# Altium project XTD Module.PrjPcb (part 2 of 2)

## Sheet IDL_17_004_A8.SchDoc: Power
size 401 x 291 mm
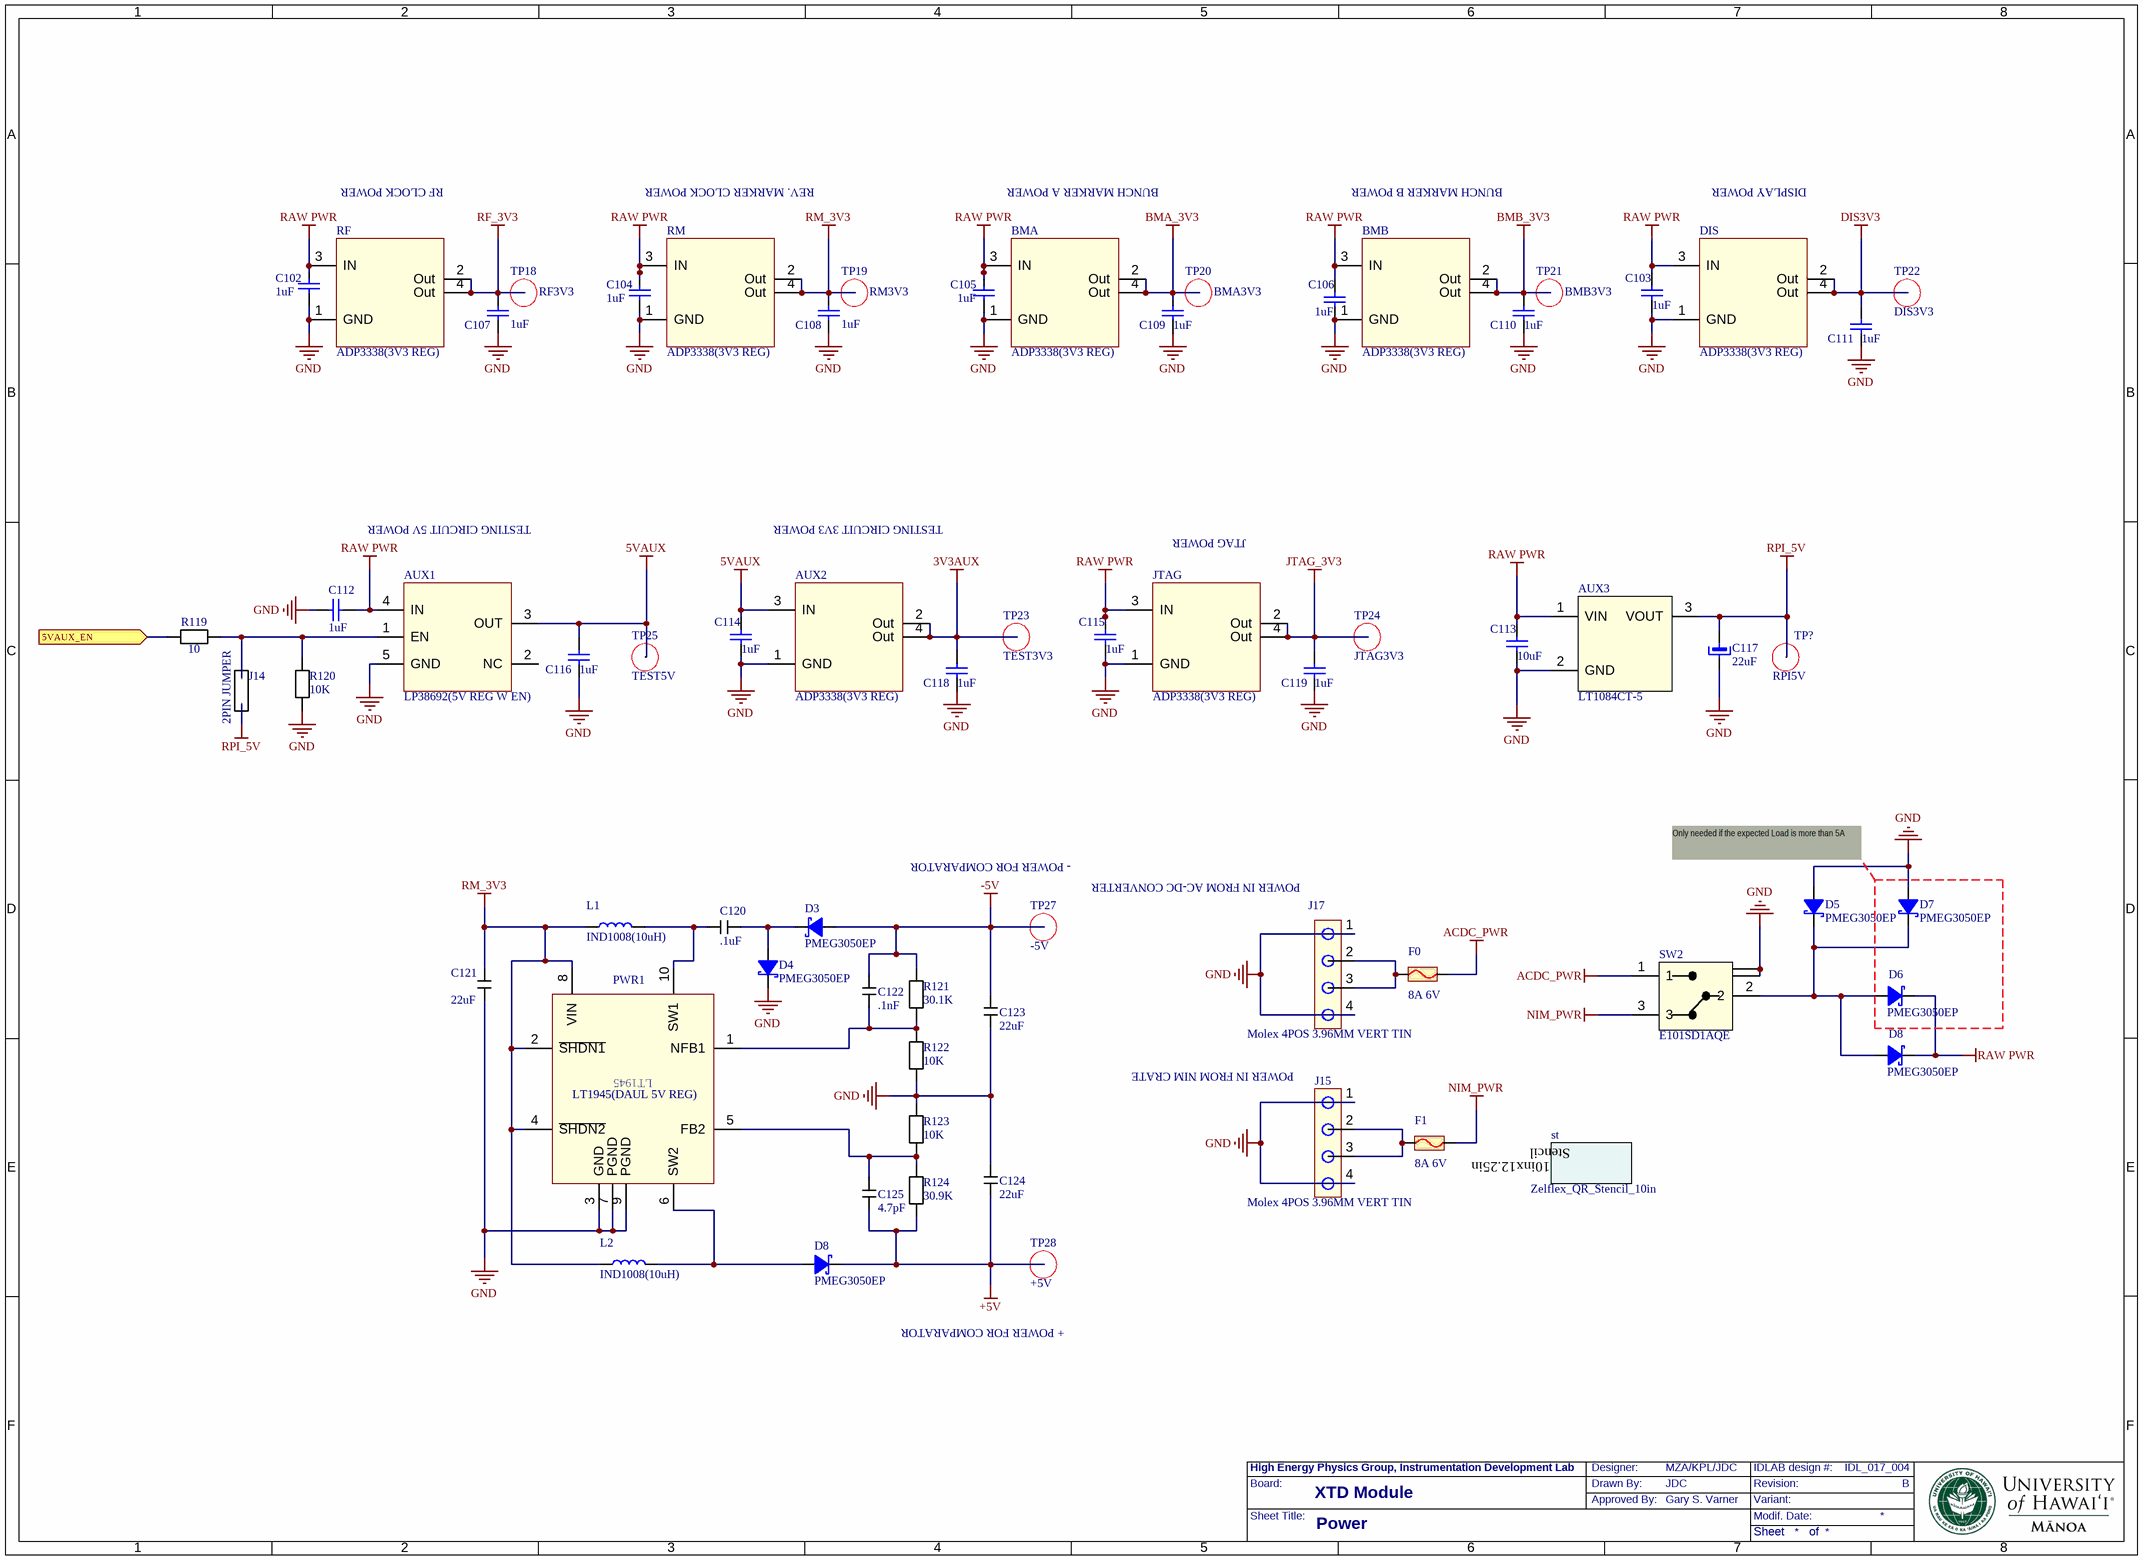
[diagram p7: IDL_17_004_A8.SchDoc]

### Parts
(Parts that share a designator on the sheet are numbered #1, #2 ... from top to bottom, then left to right.)
AUX1  LP38692(5V REG W EN)  [SOT223_5pin]
AUX2  ADP3338(3V3 REG)  [ADP3338]
AUX3  LT1084CT-5  [TO220H]
BMA  ADP3338(3V3 REG)  [ADP3338]
BMB  ADP3338(3V3 REG)  [ADP3338]
C102  1uF  [0603]
C103  1uF  [0603]
C104  1uF  [0603]
C105  1uF  [0603]
C106  1uF  [0603]
C107  1uF  [0603]
C108  1uF  [0603]
C109  1uF  [0603]
C110  1uF  [0603]
C111  1uF  [0603]
C112  1uF  [0603]
C113  10uF  [0603]
C114  1uF  [0603]
C115  1uF  [0603]
C116  1uF  [0603]
C117  22uF  [CTC-D7343-31]
C118  1uF  [0603]
C119  1uF  [0603]
C120  .1uF  [0603]
C121  22uF  [0603]
C122  .1nF  [0603]
C123  22uF  [0603]
C124  22uF  [0603]
C125  4.7pF  [0603]
D3  PMEG3050EP  [SOD128]
D4  PMEG3050EP  [SOD128]
D5  PMEG3050EP  [SOD128]
D6  PMEG3050EP  [SOD128]
D7  PMEG3050EP  [SOD128]
D8#1  PMEG3050EP  [SOD128]
D8#2  PMEG3050EP  [SOD128]
DIS  ADP3338(3V3 REG)  [ADP3338]
F0  8A 6V  [FUSE1206-1]
F1  8A 6V  [FUSE1206-1]
J14  2PIN JUMPER  [2 PIN HEADER]
J15  Molex 4POS 3.96MM VERT TIN  [Molex 4POS]
J17  Molex 4POS 3.96MM VERT TIN  [Molex 4POS]
JTAG  ADP3338(3V3 REG)  [ADP3338]
L1  IND1008(10uH)  [1008]
L2  IND1008(10uH)  [1008]
PWR1  LT1945(DAUL 5V REG)  [TFSOP_10pin]
R119  10  [0402]
R120  10K  [0402]
R121  30.1K  [0402]
R122  10K  [0402]
R123  10K  [0402]
R124  30.9K  [0402]
RF  ADP3338(3V3 REG)  [ADP3338]
RM  ADP3338(3V3 REG)  [ADP3338]
st  Zelflex_QR_Stencil_10in  [Zelflex_QR_Stencil_10in]
SW2  E101SD1AQE  [E101SD1AQE]
TP18  RF3V3  [Test Point]
TP19  RM3V3  [Test Point]
TP20  BMA3V3  [Test Point]
TP21  BMB3V3  [Test Point]
TP22  DIS3V3  [Test Point]
TP23  TEST3V3  [Test Point]
TP24  JTAG3V3  [Test Point]
TP25  TEST5V  [Test Point]
TP27  -5V  [Test Point]
TP28  +5V  [Test Point]
TP?  RPI5V  [Test Point]

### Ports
5VAUX_EN (in)

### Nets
3V3AUX: AUX2.2(Out) AUX2.4(Out) C118.2 TP23.1(TP)
5VAUX: AUX1.3(OUT) AUX2.3(IN) C114.2 C116.2 TP25.1(TP)
+5V: C124.1 C125.2 D8#2.1(C) R124.1 TP28.1(TP)
-5V: C122.2 C123.2 D3.2(A) R121.2 TP27.1(TP)
ACDC_PWR: F0.2 SW2.1
BMA_3V3: BMA.2(Out) BMA.4(Out) C109.2 TP20.1(TP)
BMB_3V3: BMB.2(Out) BMB.4(Out) C110.2 TP21.1(TP)
DIS3V3: C111.2 DIS.2(Out) DIS.4(Out) TP22.1(TP)
GND: AUX1.5(GND) AUX2.1(GND) AUX3.2(GND) BMA.1(GND) BMB.1(GND) C102.1 C103.1 C104.1 C105.1 C106.1 C107.1 C108.1 C109.1 C110.1 C111.1 C112.2 C113.1 C114.1 C115.1 C116.1 C117.2 C118.1 C119.1 C121.1 C123.1 C124.2 D4.1(C) D5.2(A) D7.2(A) DIS.1(GND) J15.1 J15.4 J17.1 J17.4 JTAG.1(GND) PWR1.3(GND) PWR1.7(PGND) PWR1.9(PGND) R120.1 R122.2 R123.1 RF.1(GND) RM.1(GND) SW2.4 SW2.5
JTAG_3V3: C119.2 JTAG.2(Out) JTAG.4(Out) TP24.1(TP)
NIM_PWR: F1.2 SW2.3
RAW PWR: AUX1.4(IN) AUX3.1(VIN) BMA.3(IN) BMB.3(IN) C102.2 C103.2 C104.2 C105.2 C106.2 C112.1 C113.2 C115.2 D6.1(C) D8#1.1(C) DIS.3(IN) JTAG.3(IN) RF.3(IN) RM.3(IN)
RF_3V3: C107.2 RF.2(Out) RF.4(Out) TP18.1(TP)
RM_3V3: C108.2 C121.2 L1.1 L2.1 PWR1.2(~{SHDN1}) PWR1.4(~{SHDN2}) PWR1.8(VIN) RM.2(Out) RM.4(Out) TP19.1(TP)
RPI_5V: AUX3.3(VOUT) C117.1 J14.2 TP?.1(TP)
Net*_36: R119.1 ; port 5VAUX_EN
NetAUX1_1: AUX1.1(EN) J14.1 R119.2 R120.2
NetC120_1: C120.1 L1.2 PWR1.10(SW1)
NetC120_2: C120.2 D3.1(C) D4.2(A)
NetC122_1: C122.1 PWR1.1(NFB1) R121.1 R122.1
NetC125_1: C125.1 PWR1.5(FB2) R123.2 R124.2
NetD5_1: D5.1(C) D6.2(A) D7.1(C) D8#1.2(A) SW2.2
NetD8#2_2: D8#2.2(A) L2.2 PWR1.6(SW2)
NetF0_1: F0.1 J17.2 J17.3
NetF1_1: F1.1 J15.2 J15.3

Not connected (* = marked no-connect by the designer): AUX1 2(NC)

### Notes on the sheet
- RF CLOCK POWER
- REV. MARKER CLOCK POWER
- BUNCH MARKER A POWER
- BUNCH MARKER B POWER
- DISPLAY POWER
- TESTING CIRCUIT 5V POWER
- TESTING CIRCUIT 3V3 POWER
- JTAG POWER
- - POWER FOR COMPARATOR
- POWER IN FROM AC-DC CONVERTER
- Only needed if the expected Load is more than 5A
- POWER IN FROM NIM CRATE
- + POWER FOR COMPARATOR

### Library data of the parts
AUX1 = LP38692(5V REG W EN): IC REG LDO 5V 0.5A SOT223-5; Manufacturer: Texas Instruments; Manufacturer part #: LP38692MPX-5.0/NOPBCT-ND
AUX2 BMA BMB DIS JTAG RF RM = ADP3338(3V3 REG): IC REG LDO 3.3V 1A SOT223-3; Manufacturer: Analog Devices Inc; Manufacturer part #: ADP3338AKCZ-3.3RL7
AUX3 = LT1084CT-5: Linear Voltage Regulator IC Positive Fixed 1 Output 5V 5A TO-220-3
C102-C116 C118 C119 = 1uF: CAP CER 1UF 25V X7R 0603; Tech: SMDR; Voltage rating: 50V
C117 = CAPT7343_22U_25V: Capacitor tantal smd 7343-31 25V 0.1Resr; Manufacturer: AVX; Manufacturer No: TPSD226K025R0100; Tech: SMDR
C120 = .1uF: CAP CER 0.1UF 50V X7R 0603; Manufacturer: Samsung Electro-Mechanics America, Inc.; Manufacturer part: CL10B104KB8SFNC
C121 C123 C124 = 22uF: CAP CER 22UF 6.3V X5R 0603; Manufacturer: Samsung Electro-Mechanics America, Inc.; Manufacturer part #: CL10A226KQ8NRNE
C122 = .1nF: CAP CER 100PF 50V NP0 0603; Manufacturer: Samsung Electro-Mechanics America, Inc.; Manufacturer part #: CL10C101JB8NNNC
C125 = 4.7pF: CAP CER 4.7PF 50V NP0 0603; Manufacturer: Samsung Electro-Mechanics America, Inc.; Manufacturer part #: CL10C4R7CB8NNNC
D3-D7 D8#1 D8#2 = D-PMEG3050EP(DIODE): Schottky diode 6A 30V 500ns 0.36Vf; Manufacturer: NXP; Manufacturer No: PMEG3050EP,115; Tech: SMDR
F0 F1 = FUSE-8A6V: Fuse 8A 6V SMDR; Manufacturer: Littelfuse; Manufacturer No: 1206L400SLWR
J14 = 2PIN JUMPER: TWO PIN JUMPER
J15 J17 = Molex 4POS 3.96MM VERT TIN: CONN HEADER 4POS 3.96MM VERT TIN; Manufacturer: Molex Inc.; Manufacturer part #: 0009652048
L1 L2 = IND1008(10uH): FIXED IND 10UH 520MA 854 MOHM; Manufacturer: TDK Corporation; Manufacturer part #: VLS252010T-100M
PWR1 = LT1945(DAUL 5V REG): IC REG BST SEPIC INV ADJ 10MSOP; Manufacturer: Linear Technology; Manufacturer part #: LT1945EMS#PBF
R119 = 10: RES SMD 10 OHM 5% 1/16W 0402; Manufacturer: Samsung Electro-Mechanics America, Inc.; Manufacturer part #: RC1005J100CS
R120 R122 R123 = 10K: RES SMD 10K OHM 5% 1/16W 0402; Manufacturer: Samsung Electro-Mechanics America, Inc.; Manufacturer part #: RC1005F4021CS
R121 = 30.1K: RES SMD 30.1K OHM 1% 1/16W 0402; Manufacturer: Samsung Electro-Mechanics America, Inc.; Manufacturer part #: RC1005F3012CS
R124 = 30.9K: RES SMD 30.9K OHM 1% 1/10W 0402; Manufacturer: Panasonic Electronic Components; Manufacturer part #: ERJ-2RKF3092X
TP18-TP25 TP27 TP28 TP? = TP: TEST POINT PC MINI .040"D BLACK; Manufacturer: Keystone Electronics; Manufacturer part #: 5001

## Sheet IDL_17_004_WD.SchDoc: XRM WRIING DIAGRAM
size 401 x 291 mm; DocumentNumber: 3; SheetNumber: 3; SheetTotal: 3
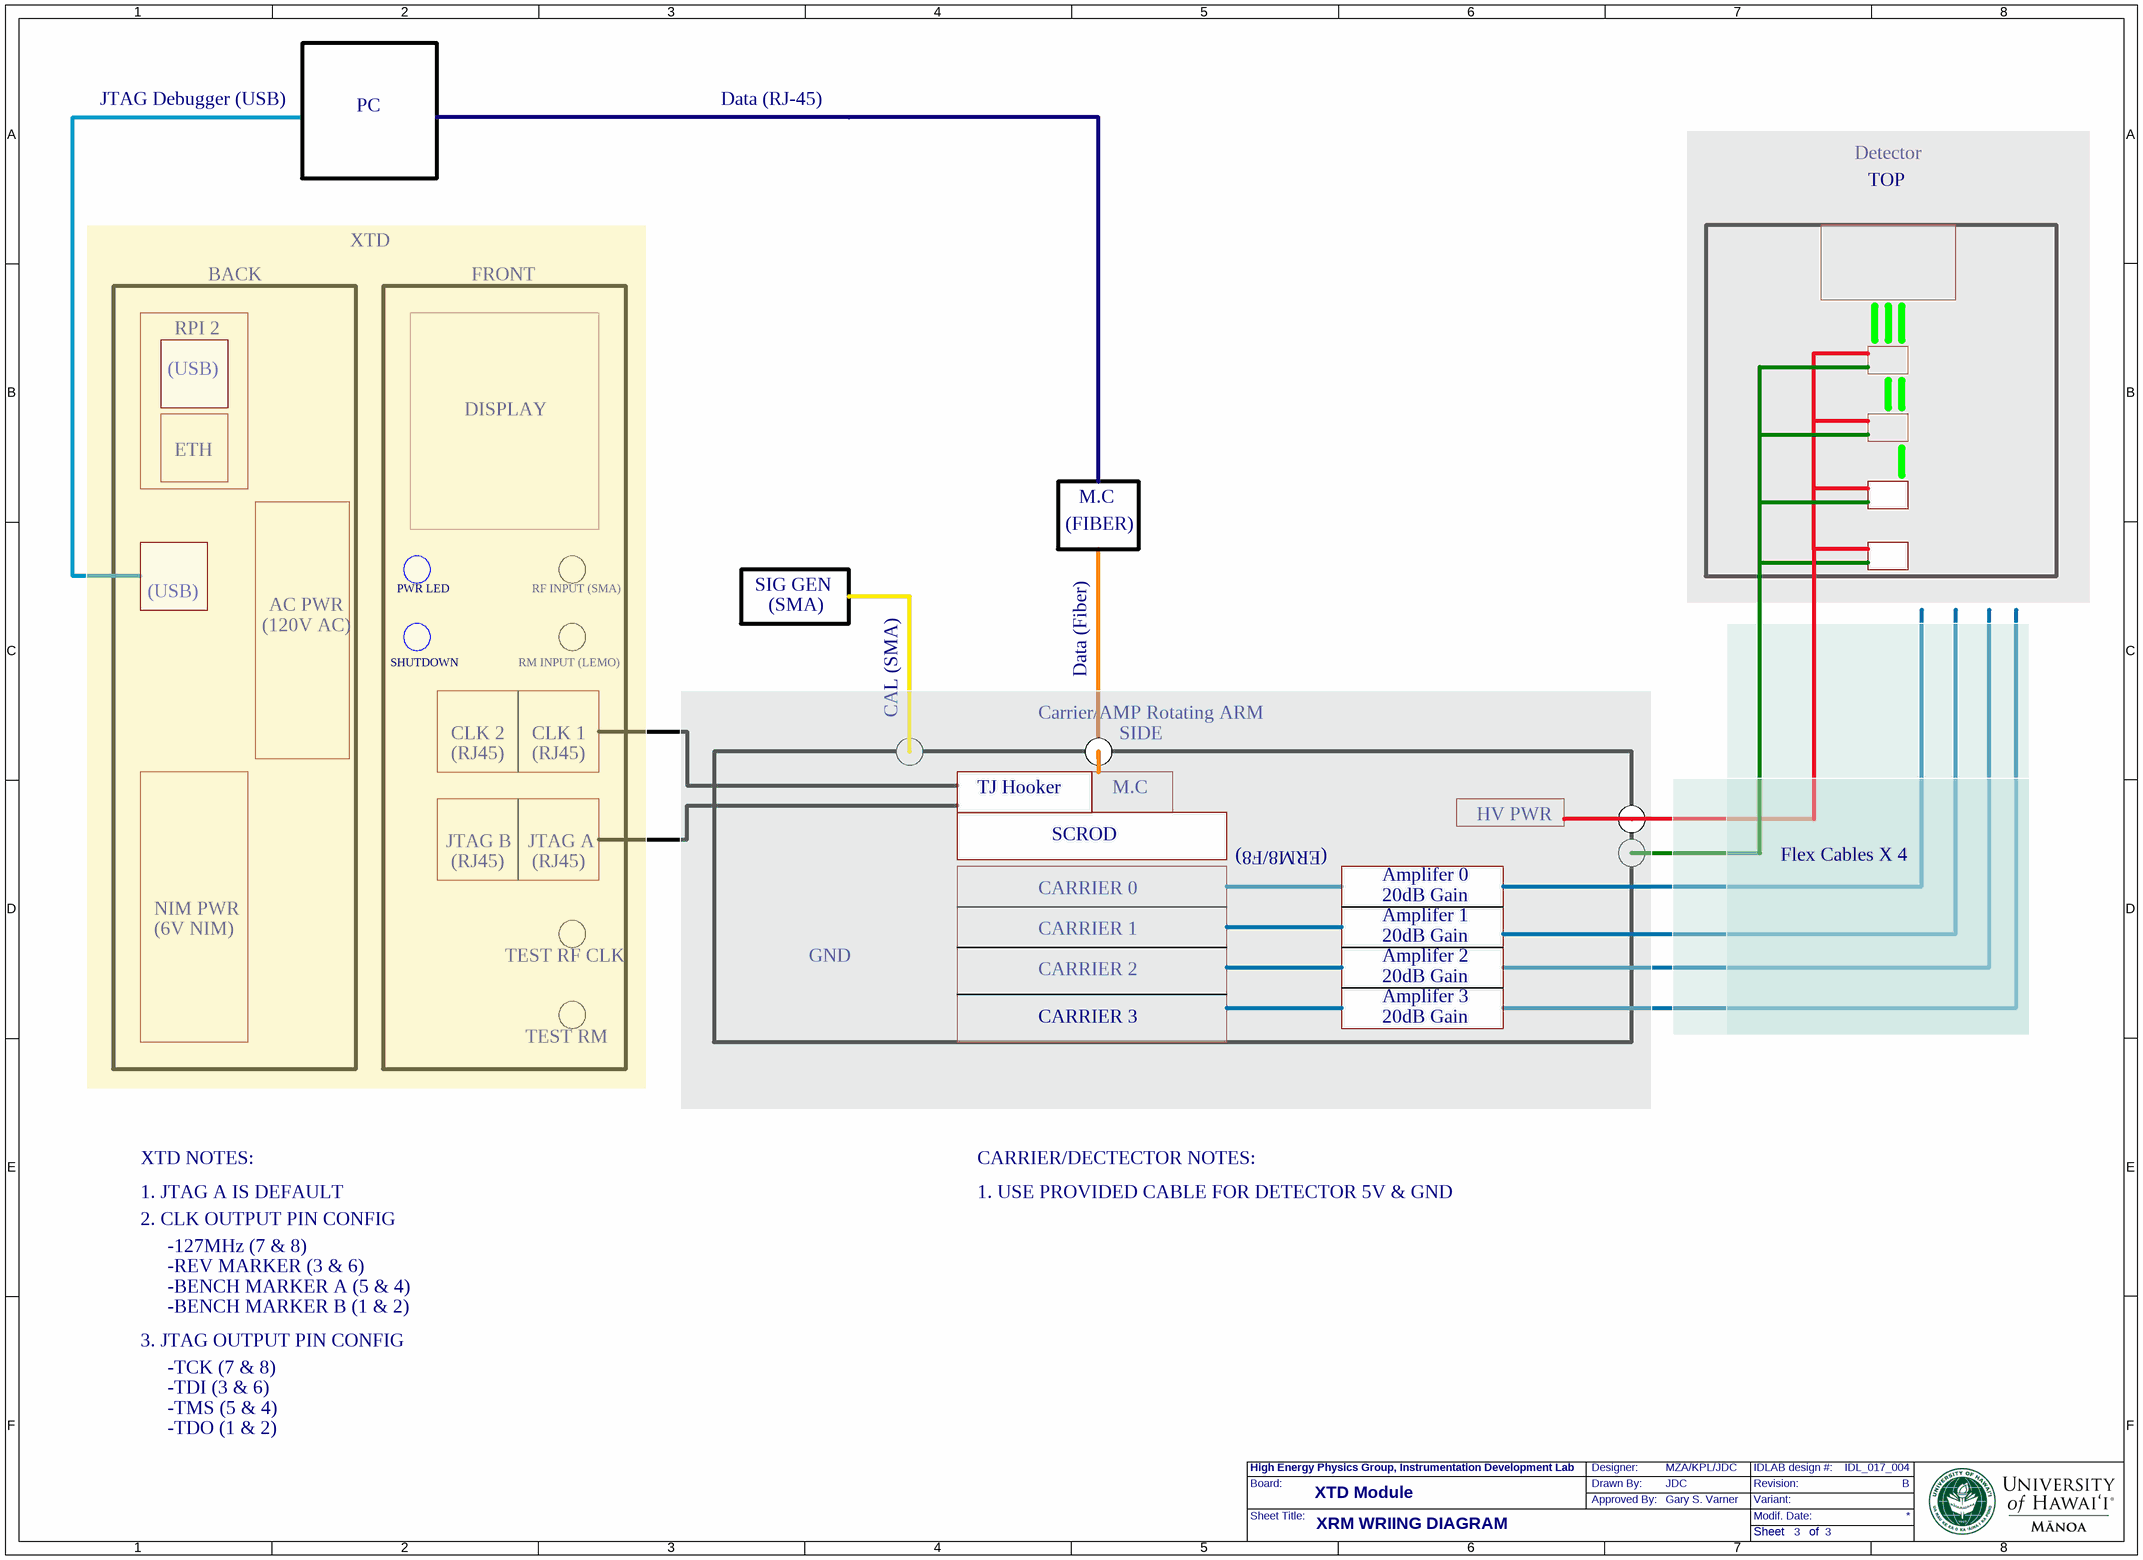
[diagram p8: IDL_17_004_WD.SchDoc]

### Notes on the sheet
- JTAG Debugger (USB)
- PC
- Data (RJ-45)
- Detector
- TOP
- BACK
- XTD
- FRONT
- RPI 2
- (USB)
- DISPLAY
- ETH
- M.C
- (FIBER)
- (120V AC)
- AC PWR
- PWR LED
- RF INPUT (SMA)
- SIG GEN
- (SMA)
- SHUTDOWN
- RM INPUT (LEMO)
- Data (Fiber)
- CLK 2
- (RJ45)
- CLK 1
- CAL (SMA)
- Carrier/AMP Rotating ARM
- SIDE
- TJ Hooker
- HV PWR
- JTAG B
- JTAG A
- CARRIER 0
- SCROD
- (ERM8/F8)
- 20dB Gain
- Amplifer 0
- Flex Cables X 4
- NIM PWR
- (6V NIM)
- TEST RF CLK
- GND
- CARRIER 1
- Amplifer 2
- Amplifer 1
- TEST RM
- CARRIER 2
- CARRIER 3
- Amplifer 3
- XTD NOTES:
- CARRIER/DECTECTOR NOTES:
- 1. JTAG A IS DEFAULT
- 2. CLK OUTPUT PIN CONFIG
- 1. USE PROVIDED CABLE FOR DETECTOR 5V & GND
- -127MHz (7 & 8)
- -REV MARKER (3 & 6)
- -BENCH MARKER A (5 & 4)
- -BENCH MARKER B (1 & 2)
- 3. JTAG OUTPUT PIN CONFIG
- -TCK (7 & 8)
- -TDI (3 & 6)
- -TMS (5 & 4)
- -TDO (1 & 2)

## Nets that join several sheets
3V3AUX: IDL_17_004_A5 (30 pins), IDL_17_004_A8 (AUX2.2 AUX2.4 C118.2 TP23.1)
5VAUX: IDL_17_004_A5 (C69.1 C71.1 POT3.1 U2.14), IDL_17_004_A8 (5 pins)
+5V: IDL_17_004_A3 (6 pins), IDL_17_004_A5 (OA1.5), IDL_17_004_A8 (5 pins)
-5V: IDL_17_004_A3 (6 pins), IDL_17_004_A5 (OA1.2), IDL_17_004_A8 (5 pins)
BMA_3V3: IDL_17_004_A4 (31 pins), IDL_17_004_A8 (BMA.2 BMA.4 C109.2 TP20.1)
BMB_3V3: IDL_17_004_A4 (31 pins), IDL_17_004_A6 (5 pins), IDL_17_004_A8 (BMB.2 BMB.4 C110.2 TP21.1)
DIS3V3: IDL_17_004_A6 (C88.1 U6.2), IDL_17_004_A8 (C111.2 DIS.2 DIS.4 TP22.1)
GND: IDL_17_004_A2 (54 pins), IDL_17_004_A3 (42 pins), IDL_17_004_A4 (56 pins), IDL_17_004_A5 (61 pins), IDL_17_004_A6 (61 pins), IDL_17_004_A7 (37 pins), IDL_17_004_A8 (45 pins)
JTAG_3V3: IDL_17_004_A6 (7 pins), IDL_17_004_A7 (31 pins), IDL_17_004_A8 (C119.2 JTAG.2 JTAG.4 TP24.1)
RAW PWR: IDL_17_004_A6 (6 pins), IDL_17_004_A8 (18 pins)
RF_3V3: IDL_17_004_A2 (43 pins), IDL_17_004_A8 (C107.2 RF.2 RF.4 TP18.1)
RM_3V3: IDL_17_004_A3 (28 pins), IDL_17_004_A8 (10 pins)
RPI_5V: IDL_17_004_A6 (9 pins), IDL_17_004_A8 (AUX3.3 C117.1 J14.2 TP?.1)
BMA1_N: IDL_17_004_A2 (J2.4), IDL_17_004_A4 (FO3.2)
BMA1_P: IDL_17_004_A2 (J2.5), IDL_17_004_A4 (FO3.1)
BMA2_N: IDL_17_004_A2 (J2.12), IDL_17_004_A4 (FO3.4 TP13.1)
BMA2_P: IDL_17_004_A2 (J2.13), IDL_17_004_A4 (FO3.3 TP12.1)
BMA_RCLK: IDL_17_004_A4 (SR1.12 SR2.12), IDL_17_004_A6 (*.13)
BMA_SRCLK: IDL_17_004_A4 (SR1.11 SR2.11), IDL_17_004_A6 (*.11)
BMB1_N: IDL_17_004_A2 (J2.2), IDL_17_004_A4 (FO4.2)
BMB1_P: IDL_17_004_A2 (J2.1), IDL_17_004_A4 (FO4.1)
BMB2_N: IDL_17_004_A2 (J2.10), IDL_17_004_A4 (FO4.4 TP16.1)
BMB2_P: IDL_17_004_A2 (J2.9), IDL_17_004_A4 (FO4.3 TP15.1)
BMB_RCLK: IDL_17_004_A4 (SR3.12 SR4.12), IDL_17_004_A6 (*.18)
BMB_SRCLK: IDL_17_004_A4 (SR3.11 SR4.11), IDL_17_004_A6 (*.15)
Net*_3: IDL_17_004_A2 (PLL1.19 R6.1), IDL_17_004_A6 (*.3)
Net*_5: IDL_17_004_A2 (PLL1.12 R7.2), IDL_17_004_A6 (*.5)
Net*_21: IDL_17_004_A2 (PLL1.8 R125.2), IDL_17_004_A6 (*.21)
Net*_29: IDL_17_004_A6 (*.29), IDL_17_004_A7 (R118.2)
Net*_36: IDL_17_004_A6 (*.36), IDL_17_004_A8 (R119.1)
RFCLK0-1_N: IDL_17_004_A2 (FO1.30), IDL_17_004_A3 (FF1.4 R19.1)
RFCLK0-1_P: IDL_17_004_A2 (FO1.31), IDL_17_004_A3 (FF1.3 R20.1)
RFCLK1-1_N: IDL_17_004_A2 (FO1.28), IDL_17_004_A3 (FF1.9 R35.2)
RFCLK1-1_P: IDL_17_004_A2 (FO1.29), IDL_17_004_A3 (FF1.8 R34.2)
RFCLK2-1_N: IDL_17_004_A2 (FO1.26), IDL_17_004_A4 (BC2.23 R60.1)
RFCLK2-1_P: IDL_17_004_A2 (FO1.27), IDL_17_004_A4 (BC2.22 R59.1)
RFCLK3-1_N: IDL_17_004_A2 (FO1.21), IDL_17_004_A4 (BC1.23 R58.1)
RFCLK3-1_P: IDL_17_004_A2 (FO1.22), IDL_17_004_A4 (BC1.22 R57.1)
RFCLK4-1_N: IDL_17_004_A2 (FO1.19), IDL_17_004_A4 (BC4.23 R77.1)
RFCLK4-1_P: IDL_17_004_A2 (FO1.20), IDL_17_004_A4 (BC4.22 R76.1)
RFCLK5-1_N: IDL_17_004_A2 (FO1.14), IDL_17_004_A4 (BC3.23 R75.1)
RFCLK5-1_P: IDL_17_004_A2 (FO1.15), IDL_17_004_A4 (BC3.22 R74.1)
RMOUT0_N: IDL_17_004_A2 (J2.14), IDL_17_004_A3 (B2.8 TP10.1)
RMOUT0_P: IDL_17_004_A2 (J2.11), IDL_17_004_A3 (B2.9 TP9.1)
RMOUT1_N: IDL_17_004_A2 (J2.6), IDL_17_004_A3 (B2.6)
RMOUT1_P: IDL_17_004_A2 (J2.3), IDL_17_004_A3 (B2.7)
RVM_FO2_P: IDL_17_004_A3 (FO2.10 R48.1 R52.2), IDL_17_004_A4 (BC3.25 BC4.25)
RVM_FO3_P: IDL_17_004_A3 (FO2.7 R50.1 R54.2), IDL_17_004_A4 (BC1.25 BC2.25)
SR_A: IDL_17_004_A4 (SR1.14), IDL_17_004_A6 (*.16)
SR_B: IDL_17_004_A4 (SR3.14), IDL_17_004_A6 (*.22)
TCK: IDL_17_004_A6 (JTAGDB.2), IDL_17_004_A7 (R114.2)
TDI: IDL_17_004_A6 (JTAGDB.3), IDL_17_004_A7 (R116.2)
TDO: IDL_17_004_A6 (JTAGDB.8), IDL_17_004_A7 (R115.2)
TMS: IDL_17_004_A6 (JTAGDB.4), IDL_17_004_A7 (R113.2)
